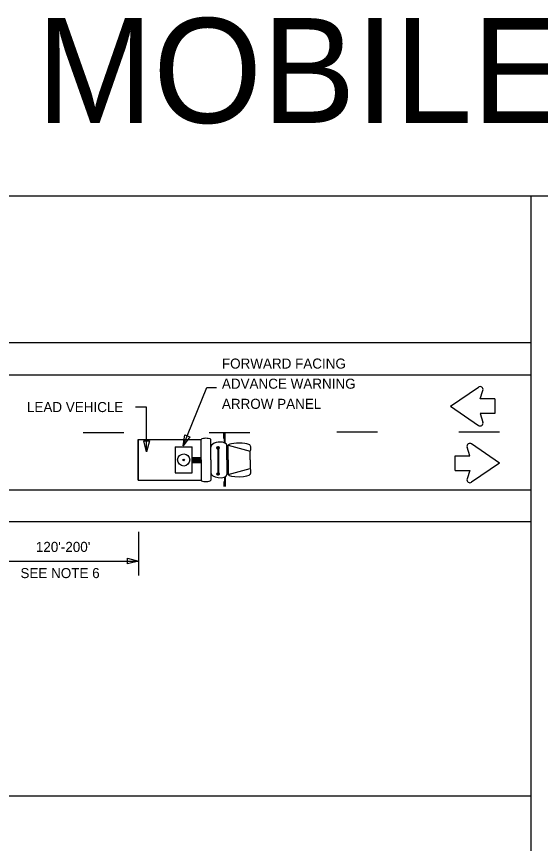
# Model space of a CAD drawing. Extents: x 1806907 to 1812607, y 675071 to 676228.
# Drawn here: x 1811449.9 to 1811762.5, y 675735.3 to 676228.4 of the extents above; entities that cross this region are included whole.
import ezdxf

# ---------------------------------------------------------------- set-up
doc = ezdxf.new("R2010")
doc.units = 0
for name, color, linetype in [('DSN_DRFT_Named-Boundary', 7, 'Continuous'), ('R_No Plot', 7, 'Continuous'), ('Working Level 1', 7, 'Continuous')]:
    doc.layers.add(name, color=color, linetype=linetype)

msp = doc.modelspace()

# ---------------------------------------------------------------- linework, layer by layer
at = {"layer": 'DSN_DRFT_Named-Boundary'}
msp.add_lwpolyline([(1810956.68, 675071.2), (1812606.68, 675071.2), (1812606.68, 676121.2), (1810956.68, 676121.2)], close=True, dxfattribs=at)
at = {"layer": 'Working Level 1'}
for p, q in [((1811756.74, 676121.2), (1811756.74, 675071.2)), ((1810956.95, 676033.93), (1811756.7, 676033.93)), ((1810956.95, 676014.8), (1811756.7, 676014.8)), ((1811708.84, 675995.97), (1811725.51, 676007.41)), ((1811726.56, 676000.34), (1811728.19, 676005.41)), ((1811735.23, 676000.34), (1811726.56, 676000.34)), ((1811735.23, 676000.34), (1811735.23, 675991.61)), ((1811708.84, 675995.97), (1811725.51, 675984.54)), ((1811735.23, 675991.61), (1811726.56, 675991.61)), ((1811726.56, 675991.61), (1811728.19, 675986.53)), ((1811573.51, 675976.83), (1811573.51, 675979.79)), ((1811573.98, 675973.97), (1811573.98, 675979.79)), ((1811574.37, 675973.97), (1811574.37, 675979.79)), ((1811522.45, 675976.1), (1811560, 675976.1)), ((1811522.45, 675951.84), (1811522.45, 675976.1)), ((1811522.45, 675976.1), (1811522.45, 675951.85)), ((1811560, 675963.97), (1811560, 675976.1)), ((1811565.75, 675963.97), (1811565.75, 675976.1)), ((1811544.51, 675971.74), (1811554.77, 675971.74)), ((1811544.51, 675971.74), (1811544.51, 675956.21)), ((1811554.77, 675956.21), (1811554.77, 675971.74)), ((1811569.42, 675971.35), (1811569.42, 675971.35)), ((1811570.04, 675971), (1811570.04, 675955.94)), ((1811570.08, 675971), (1811570.08, 675955.94)), ((1811570.12, 675971), (1811570.12, 675955.94)), ((1811570.2, 675971), (1811570.2, 675955.94)), ((1811570.3, 675971.85), (1811570.3, 675971.85)), ((1811570.32, 675971), (1811570.32, 675955.94)), ((1811575.39, 675963.97), (1811575.39, 675972.71)), ((1811576.19, 675972.71), (1811589.32, 675969.12)), ((1811576.19, 675963.97), (1811576.19, 675972.71)), ((1811720.41, 675966.48), (1811718.78, 675971.55)), ((1811738.13, 675962.11), (1811721.46, 675973.55)), ((1811554.77, 675965.53), (1811560, 675965.53)), ((1811554.77, 675964.75), (1811560, 675964.75)), ((1811589.32, 675963.97), (1811589.32, 675969.12)), ((1811711.73, 675957.75), (1811711.73, 675966.48)), ((1811711.73, 675966.48), (1811720.41, 675966.48)), ((1811554.77, 675963.97), (1811560, 675963.97)), ((1811554.77, 675963.2), (1811560, 675963.2)), ((1811554.77, 675962.42), (1811560, 675962.42)), ((1811560, 675963.97), (1811560, 675951.85)), ((1811565.75, 675963.97), (1811565.75, 675951.85)), ((1811575.39, 675963.97), (1811575.39, 675955.24)), ((1811576.19, 675963.97), (1811576.19, 675955.24)), ((1811589.32, 675963.97), (1811589.32, 675958.83)), ((1811738.13, 675962.11), (1811721.46, 675950.68)), ((1811544.51, 675956.21), (1811554.77, 675956.21)), ((1811569.46, 675955.81), (1811569.46, 675955.81)), ((1811570.34, 675956.32), (1811570.34, 675956.32)), ((1811576.19, 675955.24), (1811589.32, 675958.83)), ((1811711.73, 675957.75), (1811720.41, 675957.75)), ((1811720.41, 675957.75), (1811718.78, 675952.68)), ((1811522.45, 675951.85), (1811560, 675951.85)), ((1811573.51, 675951.12), (1811573.51, 675948.15)), ((1811573.98, 675953.98), (1811573.98, 675948.15)), ((1811574.37, 675953.98), (1811574.37, 675948.15)), ((1810956.95, 675946.11), (1811756.7, 675946.11)), ((1810956.95, 675927.23), (1811756.7, 675927.23)), ((1811522.61, 675921.17), (1811522.61, 675894.99)), ((1811439.32, 675903.7), (1811522.61, 675903.7)), ((1810956.95, 675763.73), (1811757, 675763.73))]:
    msp.add_line(p, q, dxfattribs=at)
for points in [[(1811549.33, 675972.36), (1811563.48, 676007.14), (1811569.25, 676007.14)], [(1811527.53, 675968.81), (1811527.53, 675995.51), (1811520.91, 675995.51)], [(1811489.7, 675980.35), (1811513.96, 675980.35)], [(1811564.84, 675980.35), (1811589.09, 675980.35)], [(1811640.99, 675980.68), (1811665.25, 675980.68)], [(1811713.75, 675980.68), (1811738, 675980.68)], [(1811569.4, 675971.08), (1811569.66, 675970.63)], [(1811569.42, 675971.35), (1811569.9, 675970.5)], [(1811569.48, 675971.53), (1811570.09, 675970.46)], [(1811569.57, 675971.66), (1811570.25, 675970.48)], [(1811569.68, 675971.76), (1811570.4, 675970.52)], [(1811569.8, 675971.85), (1811570.52, 675970.59)], [(1811569.94, 675971.89), (1811570.63, 675970.69)], [(1811570.09, 675971.92), (1811570.73, 675970.81)], [(1811570.28, 675971.9), (1811570.8, 675970.98)], [(1811570.49, 675971.82), (1811570.84, 675971.21)], [(1811569.44, 675955.55), (1811569.71, 675955.09)], [(1811569.46, 675955.81), (1811569.95, 675954.97)], [(1811569.52, 675956), (1811570.13, 675954.93)], [(1811569.61, 675956.13), (1811570.29, 675954.95)], [(1811569.72, 675956.23), (1811570.44, 675954.99)], [(1811569.84, 675956.31), (1811570.57, 675955.06)], [(1811569.98, 675956.35), (1811570.68, 675955.15)], [(1811570.13, 675956.39), (1811570.77, 675955.28)], [(1811570.32, 675956.37), (1811570.85, 675955.44)], [(1811570.53, 675956.29), (1811570.88, 675955.67)]]:
    msp.add_lwpolyline(points, dxfattribs=at)
for points in [[(1811529.15, 675975.31), (1811527.53, 675968.81), (1811525.9, 675975.31)], [(1811553.29, 675977.77), (1811549.33, 675972.36), (1811550.28, 675978.99)], [(1811516.11, 675905.33), (1811522.61, 675903.7), (1811516.11, 675902.08)]]:
    msp.add_lwpolyline(points, close=True, dxfattribs=at)
for centre, radius in [((1811570.11, 675971.19), 0.728), ((1811549.64, 675963.97), 3.62), ((1811549.64, 675963.97), 0.451), ((1811570.16, 675955.66), 0.728)]:
    msp.add_circle(centre, radius, dxfattribs=at)
for centre, radius, start, end in [((1811726.5, 676005.95), 1.77, 342.1824, 124.4455), ((1811726.5, 675985.99), 1.77, 235.5545, 17.8176), ((1811586.1, 675970.84), 3.64, 331.8801, 28.1199), ((1811720.46, 675972.09), 1.77, 55.5545, 197.8176), ((1811586.1, 675957.11), 3.64, 331.8801, 28.1199), ((1811720.46, 675952.14), 1.77, 162.1824, 304.4455)]:
    msp.add_arc(centre, radius, start, end, dxfattribs=at)
for centre, major_axis, ratio, start_param, end_param in [((1811562.87, 675976.1), (2.88, 0), 0.269913, 0, 3.141593), ((1811570.57, 675972.11), (4.82, 0.6), 0.503092, 0, 3.141593), ((1811582.75, 675972.63), (6.56, -0.08), 0.2034, 0, 3.141593), ((1811570.57, 675955.84), (4.82, -0.6), 0.503092, 3.141593, 6.283185), ((1811582.75, 675955.32), (6.56, 0.08), 0.2034, 3.141593, 6.283185), ((1811562.87, 675951.85), (2.88, 0), 0.269913, 3.141593, 6.283185)]:
    msp.add_ellipse(centre, major_axis=major_axis, ratio=ratio, start_param=start_param, end_param=end_param, dxfattribs=at)

# ---------------------------------------------------------------- texts
at = {"layer": 'R_No Plot'}
msp.add_text('MOBILE WZ', height=62.502, dxfattribs=at).set_placement((1811461.79, 676164.93))
at = {"layer": 'Working Level 1'}
for s, p in [('FORWARD FACING', (1811572.44, 676018.44)), ('ADVANCE WARNING ', (1811572.44, 676006.44)), ('ARROW PANEL', (1811572.44, 675994.44)), ('LEAD VEHICLE', (1811456.1, 675992.51)), ("120'-200'", (1811461.41, 675909.13)), ('SEE NOTE 6', (1811452.22, 675893.51))]:
    msp.add_text(s, height=6, dxfattribs=at).set_placement(p)

doc.saveas('drawing.dxf')
